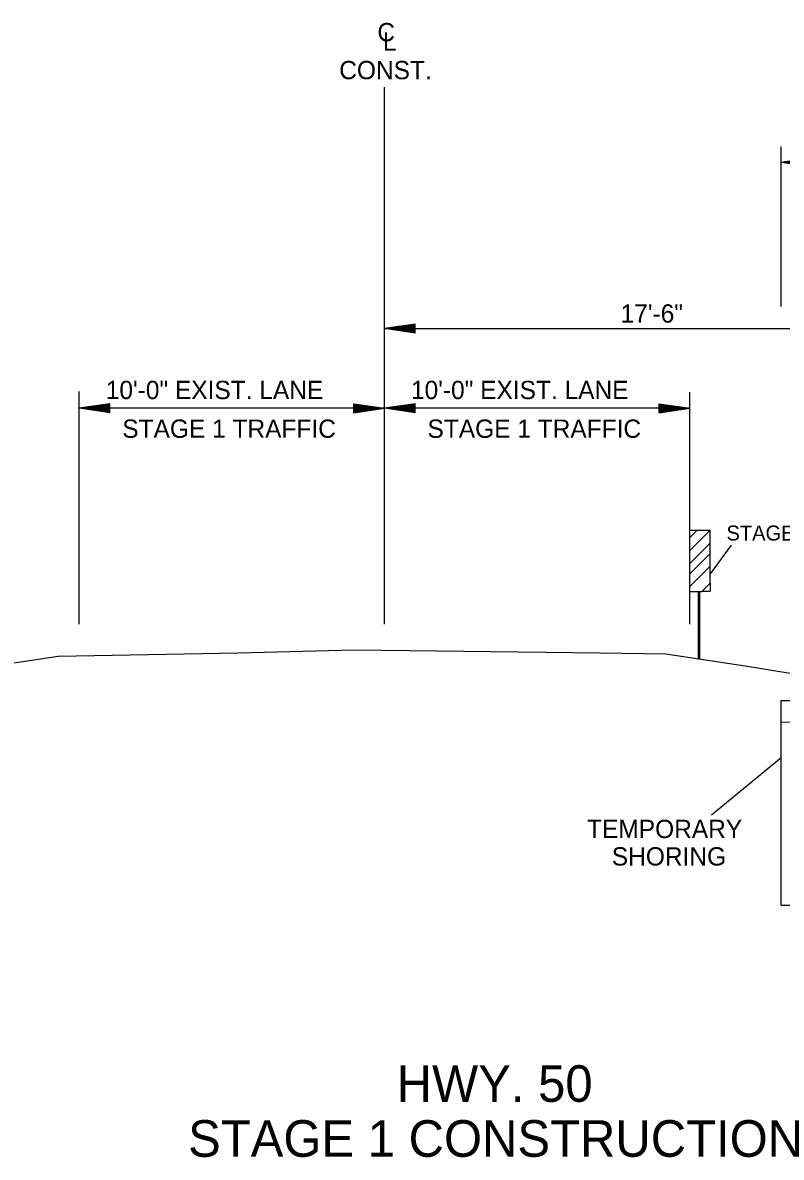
# Model space of a CAD drawing. Extents: x 2829243 to 2838161, y 467639 to 474695.
# Drawn here: x 2830142 to 2830390.5, y 467638.6 to 468010.4 of the extents above; entities that cross this region are included whole.
import ezdxf

# ---------------------------------------------------------------- set-up
doc = ezdxf.new("R2010")
doc.units = 0
for name, color, linetype in [('R_Dimension', 7, 'Continuous'), ('R_Draft', 7, 'Continuous'), ('R_Exist Surface', 7, 'Continuous'), ('R_MOT', 7, 'Continuous'), ('R_Water', 7, 'Continuous')]:
    doc.layers.add(name, color=color, linetype=linetype)

msp = doc.modelspace()

# ---------------------------------------------------------------- linework, layer by layer
at = {"layer": 'R_Dimension'}
for p, q in [((2830260.54, 467813.29), (2830260.54, 467989.25)), ((2830390.54, 467917.46), (2830390.54, 467969.89)), ((2830400.54, 467966.13), (2830390.54, 467964.63)), ((2830957.27, 467964.63), (2830390.54, 467964.63)), ((2830400.54, 467963.13), (2830390.54, 467964.63)), ((2830270.54, 467911.67), (2830260.54, 467910.17)), ((2830270.54, 467908.67), (2830270.54, 467911.67)), ((2830270.54, 467908.67), (2830260.54, 467910.17)), ((2830260.54, 467910.17), (2830435.56, 467910.17)), ((2830270.54, 467911.42), (2830262.21, 467910.17)), ((2830270.54, 467908.92), (2830262.21, 467910.17)), ((2830270.54, 467911.17), (2830263.93, 467910.17)), ((2830270.54, 467909.18), (2830263.93, 467910.17)), ((2830270.54, 467910.92), (2830265.59, 467910.17)), ((2830270.54, 467909.43), (2830265.59, 467910.17)), ((2830270.54, 467910.66), (2830267.29, 467910.17)), ((2830270.54, 467909.69), (2830267.29, 467910.17)), ((2830270.54, 467910.41), (2830268.96, 467910.17)), ((2830270.54, 467909.94), (2830268.96, 467910.17)), ((2830160.54, 467813.29), (2830160.54, 467889.56)), ((2830360.54, 467813.29), (2830360.54, 467889.31)), ((2830170.54, 467885.56), (2830160.54, 467884.06)), ((2830260.54, 467884.06), (2830160.54, 467884.06)), ((2830170.54, 467882.56), (2830160.54, 467884.06)), ((2830170.54, 467885.31), (2830162.21, 467884.06)), ((2830170.54, 467882.81), (2830162.21, 467884.06)), ((2830170.54, 467885.05), (2830163.93, 467884.06)), ((2830170.54, 467883.06), (2830163.93, 467884.06)), ((2830170.54, 467884.8), (2830165.59, 467884.06)), ((2830170.54, 467883.31), (2830165.59, 467884.06)), ((2830170.54, 467884.55), (2830167.29, 467884.06)), ((2830170.54, 467883.57), (2830167.29, 467884.06)), ((2830170.54, 467884.29), (2830168.96, 467884.06)), ((2830170.54, 467883.82), (2830168.96, 467884.06)), ((2830170.54, 467882.56), (2830170.54, 467885.56)), ((2830250.54, 467885.56), (2830260.54, 467884.06)), ((2830250.54, 467882.56), (2830250.54, 467885.56)), ((2830250.54, 467885.31), (2830258.87, 467884.06)), ((2830250.54, 467885.05), (2830257.15, 467884.06)), ((2830250.54, 467884.8), (2830255.48, 467884.06)), ((2830250.54, 467884.55), (2830253.79, 467884.06)), ((2830250.54, 467884.29), (2830252.12, 467884.06)), ((2830250.54, 467882.56), (2830260.54, 467884.06)), ((2830250.54, 467883.57), (2830253.79, 467884.06)), ((2830250.54, 467883.06), (2830257.15, 467884.06)), ((2830250.54, 467882.81), (2830258.87, 467884.06)), ((2830250.54, 467883.31), (2830255.48, 467884.06)), ((2830250.54, 467883.82), (2830252.12, 467884.06)), ((2830270.54, 467885.56), (2830260.54, 467884.06)), ((2830360.54, 467884.06), (2830260.54, 467884.06)), ((2830270.54, 467882.56), (2830260.54, 467884.06)), ((2830270.54, 467885.31), (2830262.21, 467884.06)), ((2830270.54, 467882.81), (2830262.21, 467884.06)), ((2830270.54, 467885.05), (2830263.93, 467884.06)), ((2830270.54, 467883.06), (2830263.93, 467884.06)), ((2830270.54, 467884.8), (2830265.59, 467884.06)), ((2830270.54, 467883.31), (2830265.59, 467884.06)), ((2830270.54, 467884.55), (2830267.29, 467884.06)), ((2830270.54, 467883.57), (2830267.29, 467884.06)), ((2830270.54, 467884.29), (2830268.96, 467884.06)), ((2830270.54, 467883.82), (2830268.96, 467884.06)), ((2830270.54, 467882.56), (2830270.54, 467885.56)), ((2830350.54, 467885.56), (2830360.54, 467884.06)), ((2830350.54, 467882.56), (2830350.54, 467885.56)), ((2830350.54, 467885.31), (2830358.87, 467884.06)), ((2830350.54, 467885.05), (2830357.15, 467884.06)), ((2830350.54, 467884.8), (2830355.48, 467884.06)), ((2830350.54, 467884.55), (2830353.79, 467884.06)), ((2830350.54, 467884.29), (2830352.12, 467884.06)), ((2830350.54, 467882.56), (2830360.54, 467884.06)), ((2830350.54, 467883.57), (2830353.79, 467884.06)), ((2830350.54, 467883.06), (2830357.15, 467884.06)), ((2830350.54, 467882.81), (2830358.87, 467884.06)), ((2830350.54, 467883.31), (2830355.48, 467884.06)), ((2830350.54, 467883.82), (2830352.12, 467884.06)), ((2830374.13, 467839.19), (2830367.25, 467829.84)), ((2830390.54, 467769.52), (2830367.62, 467750.74))]:
    msp.add_line(p, q, dxfattribs=at)
at = {"layer": 'R_Exist Surface'}
msp.add_lwpolyline([(2830131.04, 467799.44), (2830153.6, 467802.83), (2830212.64, 467803.95), (2830250.71, 467804.94), (2830331.24, 467803.89), (2830352.71, 467803.59), (2830380.14, 467799.45), (2830393.4, 467797.27), (2830402.14, 467793.54), (2830478.48, 467759.68), (2830504, 467759.78), (2830581.42, 467759.79), (2830615.16, 467757.94), (2830740.12, 467755.32), (2830811.85, 467755.01), (2830862.12, 467752.76), (2830887.42, 467744.44), (2830914.48, 467735.82), (2830939.25, 467732.98), (2830981.6, 467728.9), (2831040.29, 467722.85)], dxfattribs=at)
at = {"layer": 'R_MOT'}
for p, q in [((2830360.54, 467844.1), (2830363.01, 467844.1)), ((2830363.01, 467844.1), (2830360.54, 467841.67)), ((2830360.54, 467841.67), (2830360.54, 467844.1)), ((2830360.54, 467837.43), (2830367.25, 467844.1)), ((2830360.54, 467824.04), (2830360.54, 467841.67)), ((2830363.01, 467844.1), (2830367.25, 467844.1)), ((2830367.25, 467826.75), (2830367.25, 467844.1)), ((2830367.25, 467839.89), (2830360.54, 467833.22)), ((2830360.54, 467833.22), (2830360.54, 467837.43)), ((2830367.25, 467836.48), (2830360.54, 467829.8)), ((2830367.25, 467832.31), (2830367.25, 467836.48)), ((2830360.54, 467825.62), (2830367.25, 467832.31)), ((2830364.54, 467824.04), (2830367.25, 467826.75)), ((2830367.25, 467826.75), (2830367.25, 467824.04)), ((2830360.54, 467824.04), (2830364.54, 467824.04)), ((2830363.36, 467801.9), (2830363.36, 467823.87)), ((2830363.88, 467801.9), (2830363.88, 467823.87)), ((2830367.25, 467824.04), (2830364.54, 467824.04))]:
    msp.add_line(p, q, dxfattribs=at)
at = {"layer": 'R_Water'}
for p, q in [((2830390.54, 467788.34), (2830677.8, 467788.1)), ((2830390.54, 467721.26), (2830390.54, 467788.34)), ((2830390.54, 467781.26), (2830687.8, 467781.01)), ((2830390.54, 467721.26), (2830887.09, 467720.85))]:
    msp.add_line(p, q, dxfattribs=at)

# ---------------------------------------------------------------- texts
at = {"layer": 'R_Dimension'}
for s, p in [('C', (2830258.19, 468004.32)), ('L', (2830260, 468001.27)), ('CONST.', (2830245.7, 467991.89)), ('17\'-6"', (2830337.89, 467912.13)), ('10\'-0" EXIST. LANE', (2830169.21, 467887.06)), ('10\'-0" EXIST. LANE', (2830269.21, 467887.06)), ('STAGE 1 TRAFFIC', (2830174.62, 467874.38)), ('STAGE 1 TRAFFIC', (2830274.62, 467874.38)), ('TEMPORARY', (2830326.91, 467743.22)), ('SHORING', (2830335.01, 467734.22))]:
    msp.add_text(s, height=6, dxfattribs=at).set_placement(p)
at = {"layer": 'R_Draft'}
for s, height, p in [('STAGE 1: VERTICAL PANEL', 4.9184, (2830372.58, 467840.72)), ('HWY. 50', 12, (2830264.51, 467656.78)), ('STAGE 1 CONSTRUCTION', 12, (2830196.19, 467638.78))]:
    msp.add_text(s, height=height, dxfattribs=at).set_placement(p)

doc.saveas('drawing.dxf')
